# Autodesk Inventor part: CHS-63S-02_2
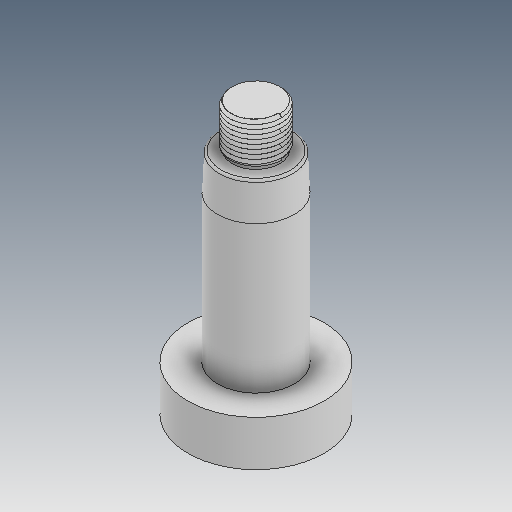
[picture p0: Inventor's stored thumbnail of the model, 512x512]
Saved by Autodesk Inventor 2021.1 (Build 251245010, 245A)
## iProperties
Created: 2019-05
Part Number: CHS-63S-02_2
Material: Ogólny
Document SubType Name: Modeling
Designer: user
Density: 1 g/cm^3
Appearance: Domyślna
Author: user
Revision Number: ÈÎºÎ
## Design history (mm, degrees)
feature "ÊäÈë1"
feature "ÊäÈë2"
node "Bryła1"
node "Bryła2"
